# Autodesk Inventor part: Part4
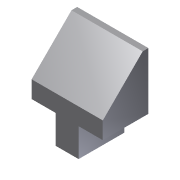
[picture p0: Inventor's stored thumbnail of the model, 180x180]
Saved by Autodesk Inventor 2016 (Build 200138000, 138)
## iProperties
Shininess: 77.0
Length Units: 11269
Angle Units: 11279
Time Units: 11290
Mass Units: 11283
Length Display Precision: 3
Angle Display Precision: 2
Created: 2002-01
Part Number: Part4
Document SubType Name: Modeling
Designer: ***
Density: 1 g/cm^3
Material: Generic
Appearance: Default
Density: 0.0
Volumn: 0.0
Area: 0.0
PropertySet Name: Model Information
Control State: 0
Master: False
Checked Out: False
Author: ***
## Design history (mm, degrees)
sketch "Sketch2"
  geometry: L1 (2.32, -6.969)-(2.32, 13.031); L2 (2.32, 13.031)-(0.32, 13.031); L3 (0.32, 13.031)-(-13.68, -0.969); L4 (-13.68, -0.969)-(-13.68, -6.969); L5 (-13.68, -6.969)-(2.32, -6.969)
  constraints: 10 end point, 2 parallel, 1 perpendicular, 1 vertical
  dimensions: "d0" = 2 distance of L1.end L2.end; "d1" = 135 deg angle of L4 L3; "d2" = 20 distance of L1.start L1.end; "d3" = 16 distance of L4.end L1.start
extrude "Extrusion1" new body sketch "Sketch2" stored distance "d4" = 25; taper "d5" = 0 deg
sketch "Sketch3"
  geometry: L1 (-13.68, -6.969)-(2.32, -6.969); L2 (2.32, -6.969)-(2.32, -16.969); L3 (2.32, -16.969)-(-13.68, -16.969); L4 (-13.68, -16.969)-(-13.68, -6.969); L5 (-13.68, -6.969)-(2.32, -6.969) reference; L6 (-13.68, -0.969)-(-13.68, -6.969) reference; L7 (2.32, -6.969)-(2.32, 13.031) reference
  constraints: 8 end point, 3 collinear, 2 parallel, 1 horizontal, 1 perpendicular
  dimensions: "d6" = 10 distance of L3.end L1.start
extrude "Extrusion2" join sketch "Sketch3" stored distance "d7" = 8; taper "d8" = 0 deg
body "Solid1"
